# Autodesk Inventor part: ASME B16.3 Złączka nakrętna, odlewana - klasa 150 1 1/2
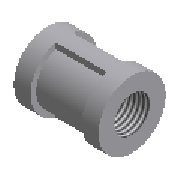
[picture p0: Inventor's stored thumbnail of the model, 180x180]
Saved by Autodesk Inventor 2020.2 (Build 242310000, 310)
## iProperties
Manager: www.cadconsulting.pl
Company: Fabian Stasiak CAD Consulting
IsCustomPart: 0
Created: 2014-02
Part Number: ASME B16.3 Złączka nakrętna, odlewana - klasa 150 1 1/2
Material: Żelazo, ciągliwe
Description: Złączka nakrętna
Document SubType Name: Modeling
Standard: ASME B16.3
Designer: F.Stasiak
Standard Revision: 1988
Standards Organization: ANSI
Language: pl-PL
Size Designation: 1 1/2
Categories: <MemberInstance><Categories><Category DisplayName="Rury cienko- i grubościenne" InternalName="4347fa0f-2144-441d-94cd-e3e15c92b736" Mnemonic="TUBEANDPIPE"><Cate
Density: 7.15 g/cm^3
Appearance: Częściowo polerowana
Catalog Web Link: www.expertbooks.pl
NAME: PIPING: ASME B16.3 Cast Coupling - Class 150
DATA: <meta><inlinegroups number="1" deflen="2.6924"></inlinegroups><connections number="2"></connections><angles><a>3.14159265358979</a></angles></meta>
Author: F.Stasiak
Subject: Zbiór ćwiczeń. Autodesk Inventor 2020. Kurs Professional
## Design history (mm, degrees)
sketch "Sketch1"
  geometry: L1 (0, 0)-(54.61, 0); L2 (54.61, 22.26)-(54.61, 30.861); L3 (54.61, 30.861)-(45.212, 30.861); L4 (45.212, 30.861)-(45.212, 27.728); L5 (45.212, 27.728)-(9.398, 27.728); L6 (9.398, 27.728)-(9.398, 30.861); L7 (9.398, 30.861)-(0, 30.861); L8 (36.83, 21.705)-(54.61, 22.26); L9 (54.61, 22.26)-(54.61, 0); L10 (27.305, 0)-(27.305, 27.728); L11 (0, 22.26)-(0, 30.861); L12 (0, 30.861)-(9.398, 30.861); L13 (9.398, 30.861)-(9.398, 27.728); L14 (17.78, 21.705)-(0, 22.26); L15 (0, 22.26)-(0, 0); L16 (17.78, 21.705)-(36.83, 21.705); L17 (17.78, 21.705)-(17.78, 0); L18 (36.83, 21.705)-(36.83, 0); 1 further point
  constraints: 36 end point, 6 perpendicular, 2 collinear, 2 midpoint, 2 parallel, 2 point on line, 2 symmetric about line, 1 coincident, 1 horizontal, 5 other
  dimensions: "d0" = 61.722 diameter of L7.end L1 (= H); "d1" = 9.398 distance of L3.end L2.end (= E1); "d2" = 44.52036 diameter of L2.start L1 (= MD); "d3" = 3.13267 distance of L3.end L4.end (= 0.333333 x E1); "d9" = 54.61 distance of L2.end L7.end (= W1); "d10" = 17.78 horizontal distance of L8.start L2.start (= B); "d13" = 1.78991 deg angle of L1 L8
revolve "Revolution1" sketch "Sketch1" stored, may be unused: angle "d8" = 90 deg
sketch "Sketch2"
  geometry: L1 (0, 30.861)-(0, 27.728); L2 (-5.461, 27.185)-(-5.461, 30.374); L3 (5.461, 27.185)-(5.461, 30.374); A1 r 30.861 centre (0, 0) between (5.461, 30.374) and (-5.461, 30.374); A2 r 27.728 centre (0, 0) between (5.461, 27.185) and (-5.461, 27.185); 3 further points
  constraints: 6 end point, 4 point on circle, 2 centre point, 2 vertical alignment, 1 coincident, 1 parallel, 1 symmetric about line, 1 vertical, 7 other
  dimensions: "d6" = 10.922 diameter of L3 L1 (= 0.2 x W1)
extrude "Extrusion1" join sketch "Sketch2" taper "d7" = 0 deg; stored distance "d18" = 44.52036 (= MD)
mirror "Mirror1"
workpoint "Work Point1"
workpoint "Work Point2"
workaxis "Work Axis1"
workpoint "Work Point3"
workaxis "Work Axis2"
workpoint "Work Point4"
body "Solid1"
feature "Gwint1" dims "d4" = 17.78 (= B), "d5" = 0
feature "Gwint2" dims "d11" = 17.78 (= B), "d12" = 0
other parameters: "H" = 61.722 [user parameter; used in 1 equation term], "MD" = 44.52036 [user parameter; used in 2 equation terms], "W1" = 54.61 [user parameter; used in 2 equation terms], "E1" = 9.398 [user parameter; used in 2 equation terms], "B" = 17.78 [user parameter; used in 3 equation terms], "Size_Designation" = 15 [user parameter]
